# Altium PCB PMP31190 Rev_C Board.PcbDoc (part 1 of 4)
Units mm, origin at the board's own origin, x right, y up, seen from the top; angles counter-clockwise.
Board outline 175.26 x 91.44 mm, 4 copper layers (Top Layer, Mid-Layer 1, Mid-Layer 2, Bottom Layer), stack 1.473 mm thick; 252 components, 140 nets, 735 pads, 501 vias.
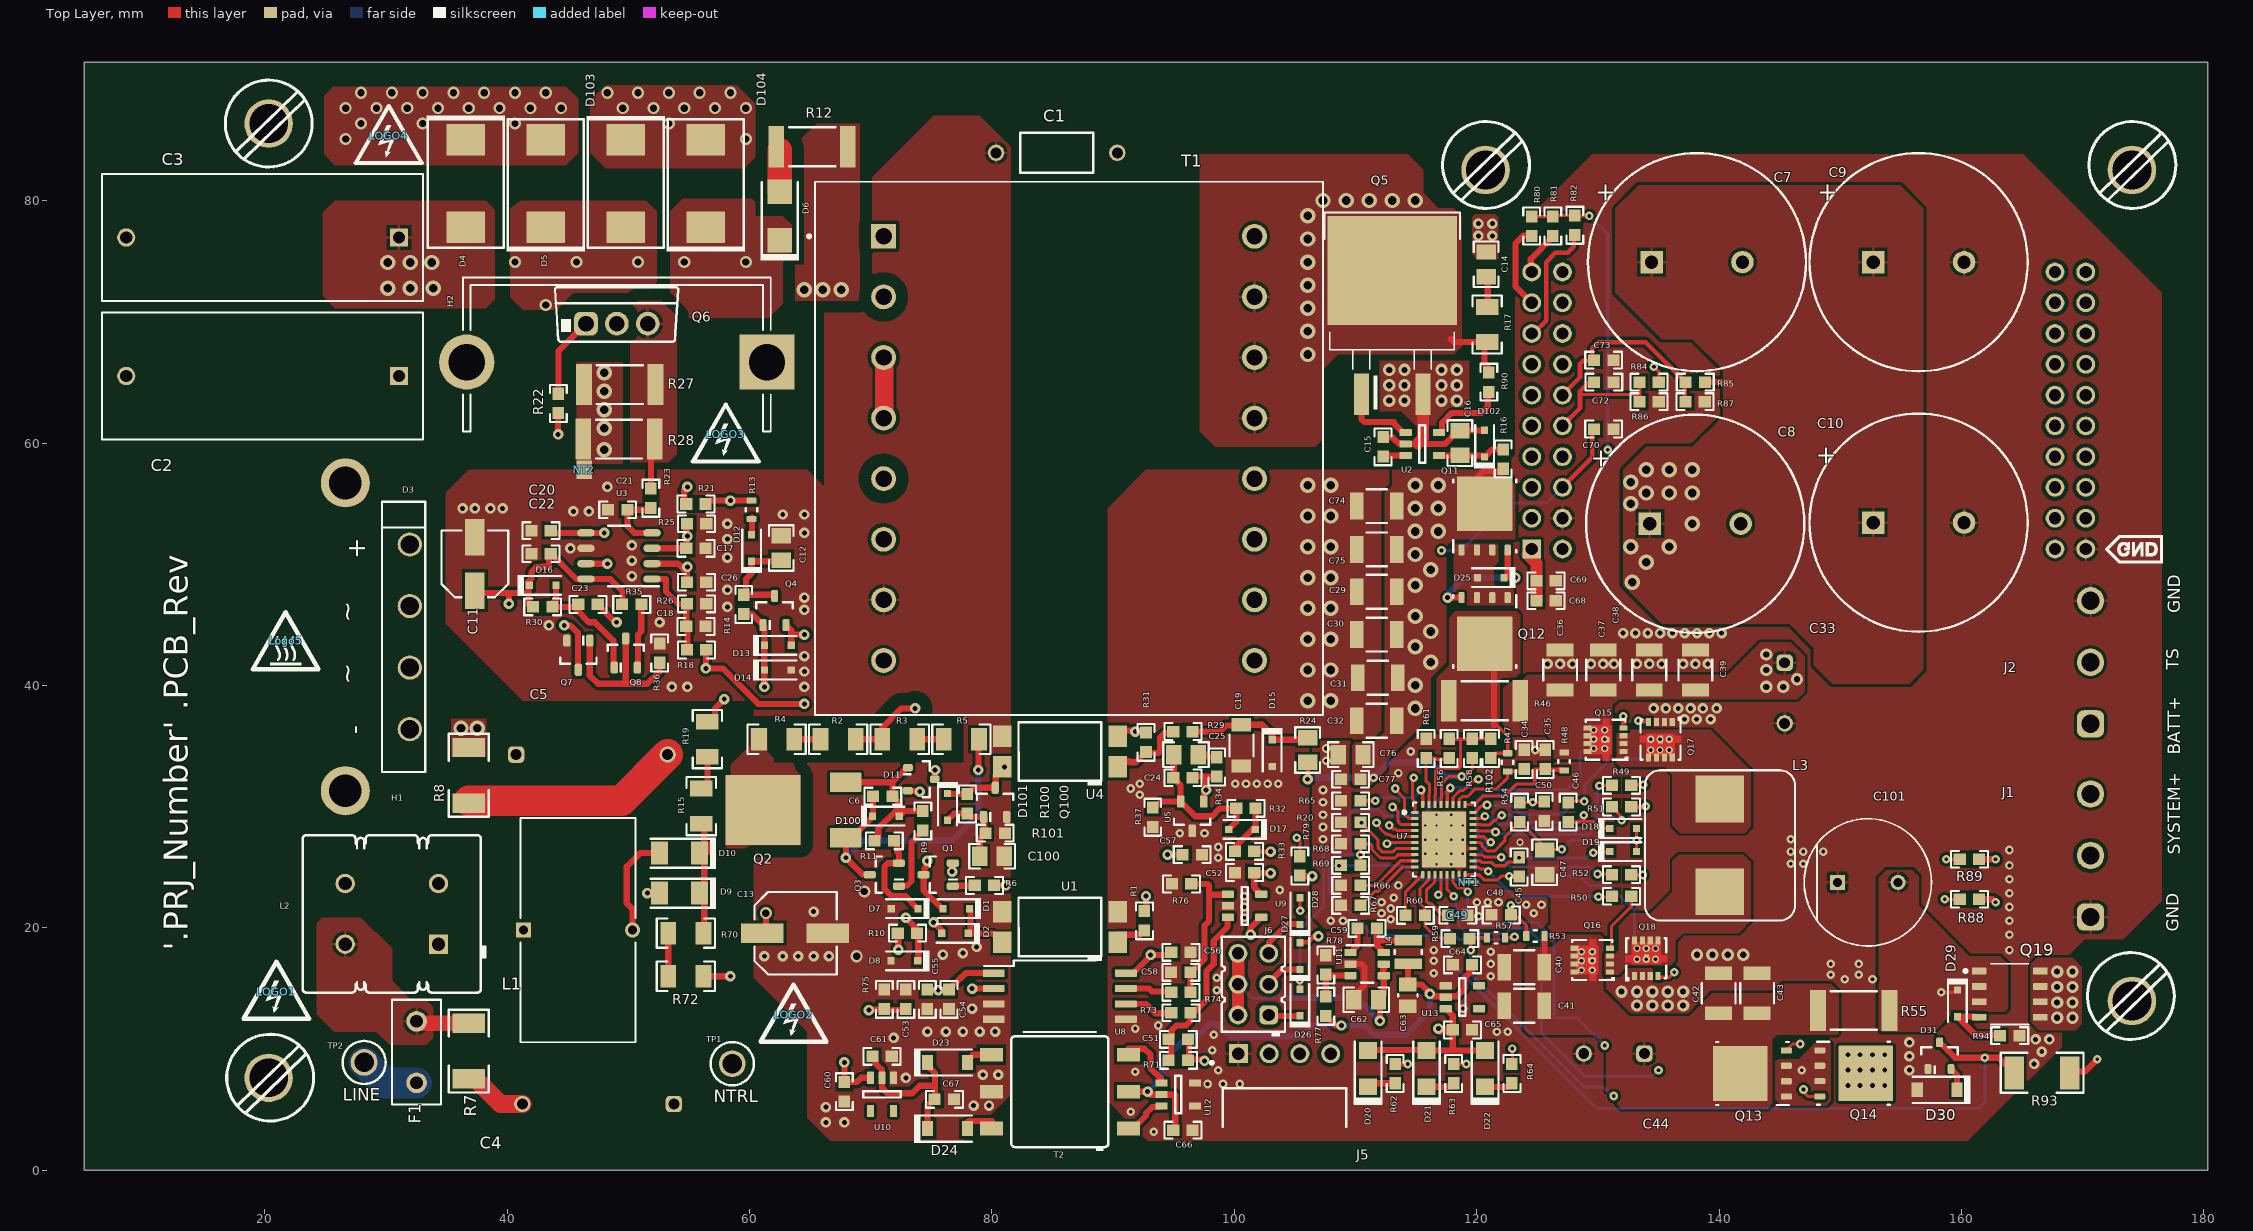
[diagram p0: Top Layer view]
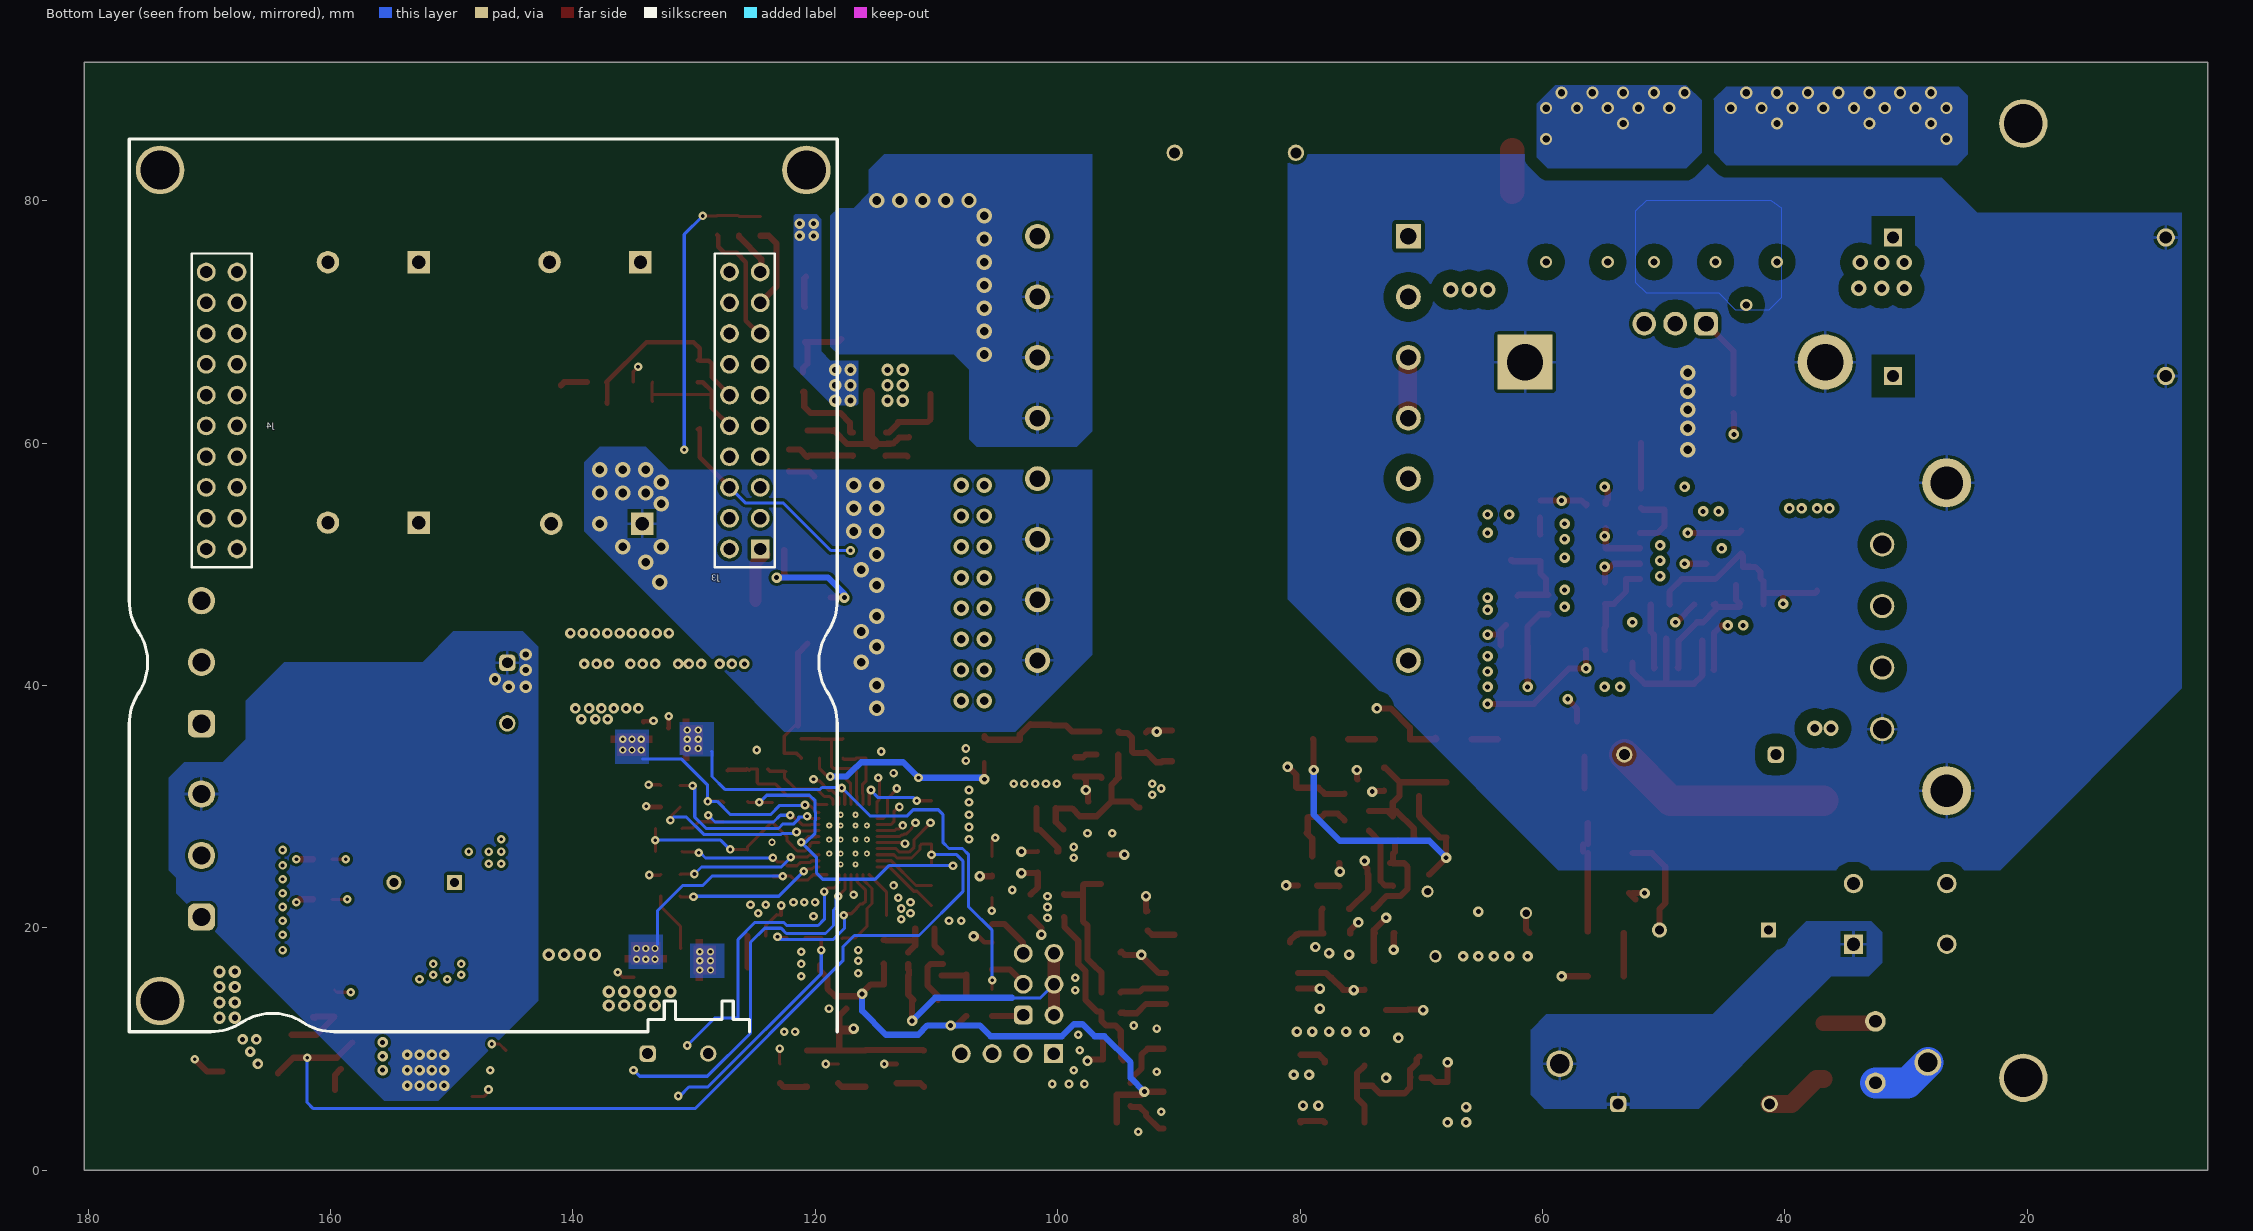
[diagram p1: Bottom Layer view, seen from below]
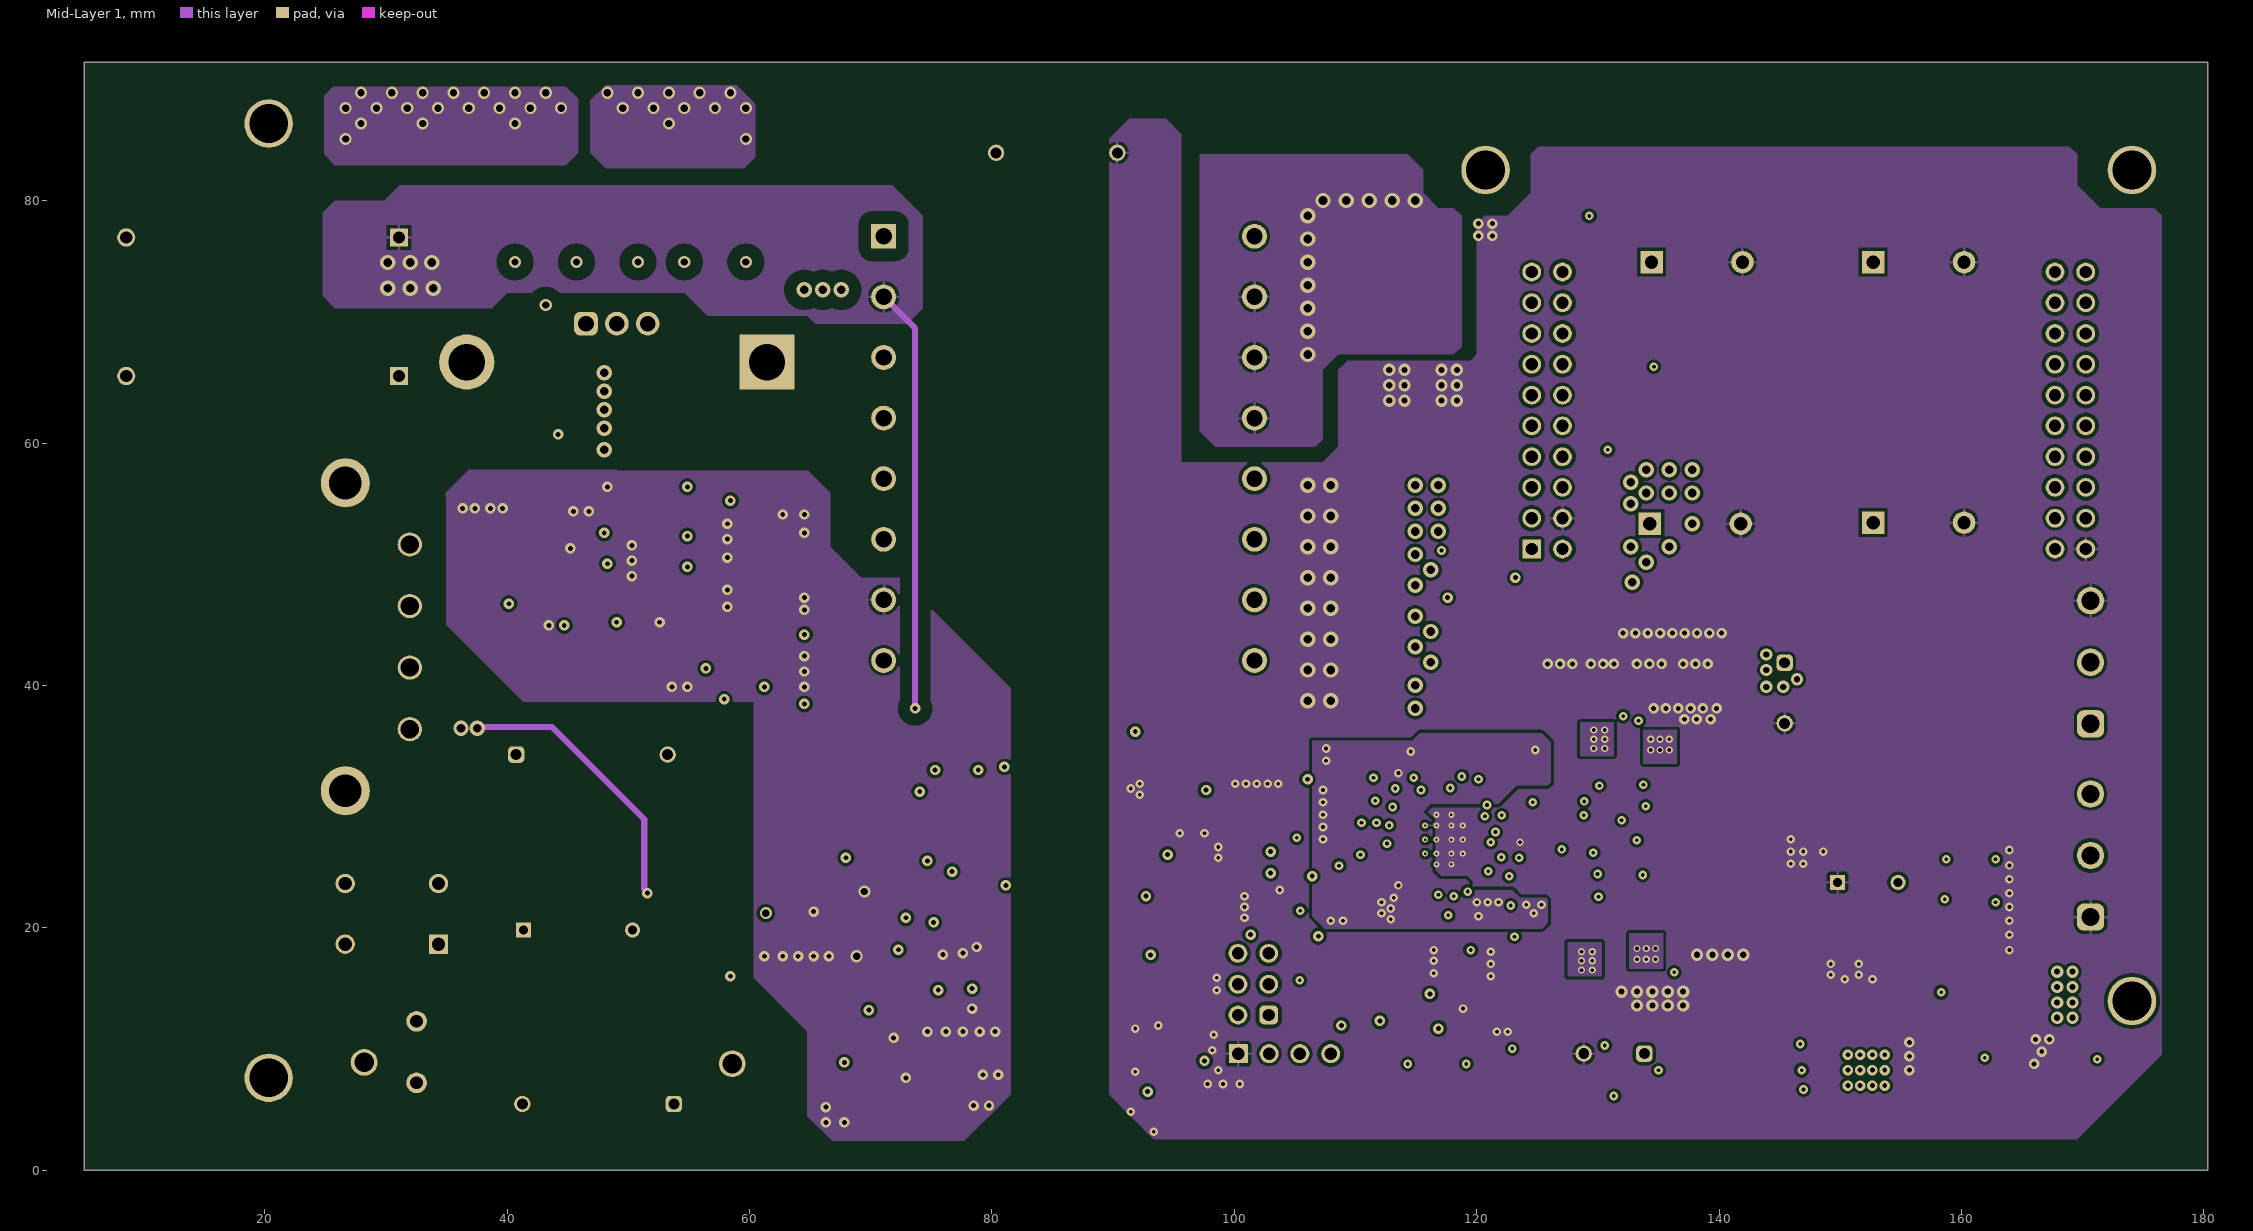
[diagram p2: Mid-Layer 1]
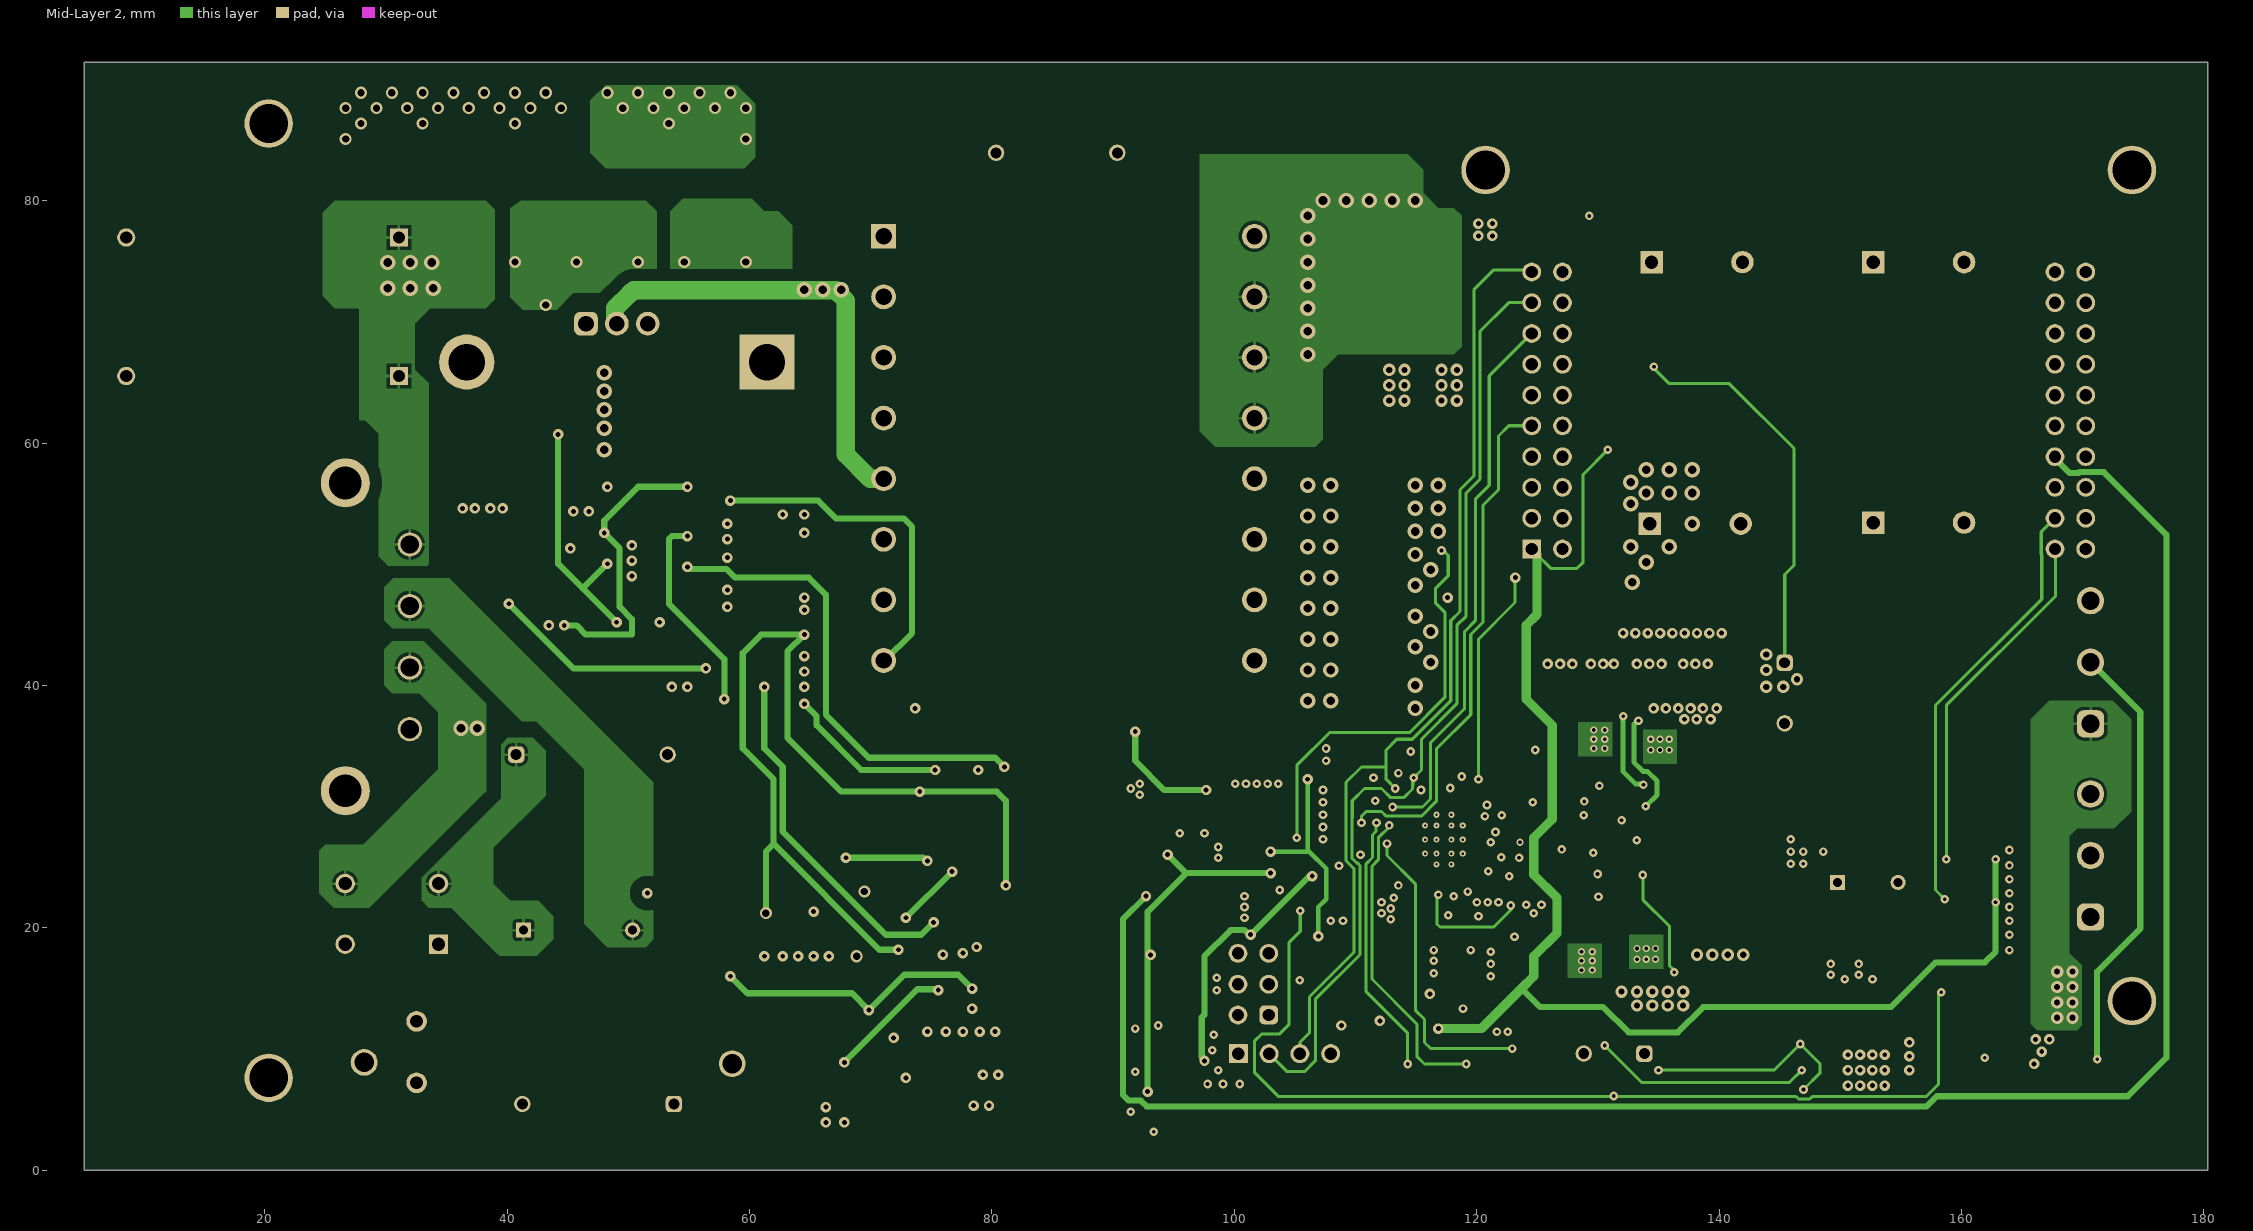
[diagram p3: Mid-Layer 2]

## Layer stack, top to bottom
Top Solder: solder mask 0.18, Solder Resist, Dk 3.5
Top Layer: signal copper 0.07
Dielectric1: prepreg 0.232, FR-4, Dk 4.8
Mid-Layer 1: signal copper 0.0356
Dielectric2: dielectric 0.71, FR-4, Dk 4.8
Mid-Layer 2: signal copper 0.0356
Dielectric3: dielectric 0.32, FR-4, Dk 4.8
Bottom Layer: signal copper 0.07
Bottom Solder: solder mask 0.018, Solder Resist, Dk 3.5

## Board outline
5.08,0 180.34,0 180.34,46.99 180.34,91.44 5.08,91.44

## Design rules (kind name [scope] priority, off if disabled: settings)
AcuteAngle [All] p1: minimum=4.50000000000000E+0001 checktracksonly=FALSE
AssemblyTestPointUsage [All] p1: valid=2
BoardOutlineClearance [All] p1: gap=0.381 ignorepadtopadclearanceinfootprint=FALSE
Clearance "Schematic Clearance Constraint_24" [InNet('NetD5_1')] p1: gap=1.016 ignorepadtopadclearanceinfootprint=FALSE
Clearance "Schematic Clearance Constraint_23" [InNet('NetD103_1')] p2: gap=1.016 ignorepadtopadclearanceinfootprint=FALSE
Clearance "Schematic Clearance Constraint_19" [InNet('PFC_off')] p3: gap=0.229 ignorepadtopadclearanceinfootprint=FALSE
Clearance "Schematic Clearance Constraint_18" [InNet('NetJ2_1')] p4: gap=0.229 ignorepadtopadclearanceinfootprint=FALSE
Clearance "Schematic Clearance Constraint_11" [InNet('BAT')] p5: gap=0.254 ignorepadtopadclearanceinfootprint=FALSE
Clearance "Schematic Clearance Constraint_10" [InNet('NetD30_1')] p6: gap=0.229 ignorepadtopadclearanceinfootprint=FALSE
Clearance "Schematic Clearance Constraint_4" [InNet('NetD29_2')] p7: gap=0.229 ignorepadtopadclearanceinfootprint=FALSE
Clearance "Schematic Clearance Constraint" [InNet('NetJ2_2')] p8: gap=0.229 ignorepadtopadclearanceinfootprint=FALSE
Clearance "Schematic Clearance Constraint_170" [InNet('NetQ18_4')] p9: gap=0.229 ignorepadtopadclearanceinfootprint=FALSE
Clearance "Schematic Clearance Constraint_169" [InNet('NetR52_2')] p10: gap=0.229 ignorepadtopadclearanceinfootprint=FALSE
Clearance "Schematic Clearance Constraint_168" [InNet('SDA')] p11: gap=0.229 ignorepadtopadclearanceinfootprint=FALSE
Clearance "Schematic Clearance Constraint_167" [InNet('NetC72_1')] p12: gap=0.229 ignorepadtopadclearanceinfootprint=FALSE
Clearance "Schematic Clearance Constraint_166" [InNet('NetC34_2')] p13: gap=0.229 ignorepadtopadclearanceinfootprint=FALSE
Clearance "Schematic Clearance Constraint_165" [InNet('NetJ4_39')] p14: gap=0.229 ignorepadtopadclearanceinfootprint=FALSE
Clearance "Schematic Clearance Constraint_164" [InNet('NetC45_1')] p15: gap=0.229 ignorepadtopadclearanceinfootprint=FALSE
Clearance "Schematic Clearance Constraint_163" [InNet('NetR66_2')] p16: gap=0.229 ignorepadtopadclearanceinfootprint=FALSE
Clearance "Schematic Clearance Constraint_162" [InNet('NetR60_2')] p17: gap=0.229 ignorepadtopadclearanceinfootprint=FALSE
Clearance "Schematic Clearance Constraint_161" [InNet('NetC49_1')] p18: gap=0.229 ignorepadtopadclearanceinfootprint=FALSE
Clearance "Schematic Clearance Constraint_160" [InNet('NetR63_2')] p19: gap=0.229 ignorepadtopadclearanceinfootprint=FALSE
Clearance "Schematic Clearance Constraint_159" [InNet('NetR58_1')] p20: gap=0.229 ignorepadtopadclearanceinfootprint=FALSE
Clearance "Schematic Clearance Constraint_158" [InNet('NetC48_2')] p21: gap=0.229 ignorepadtopadclearanceinfootprint=FALSE
Clearance "Schematic Clearance Constraint_157" [InNet('NetC73_1')] p22: gap=0.229 ignorepadtopadclearanceinfootprint=FALSE
Clearance "Schematic Clearance Constraint_155" [InNet('BAT_DRV')] p23: gap=0.229 ignorepadtopadclearanceinfootprint=FALSE
Clearance "Schematic Clearance Constraint_154" [InNet('NetR67_2')] p24: gap=0.229 ignorepadtopadclearanceinfootprint=FALSE
Clearance "Schematic Clearance Constraint_153" [InNet('NetR49_1')] p25: gap=0.229 ignorepadtopadclearanceinfootprint=FALSE
Clearance "Schematic Clearance Constraint_152" [InNet('NetC46_2')] p26: gap=0.229 ignorepadtopadclearanceinfootprint=FALSE
Clearance "Schematic Clearance Constraint_151" [InNet('NetQ17_4')] p27: gap=0.229 ignorepadtopadclearanceinfootprint=FALSE
Clearance "Schematic Clearance Constraint_150" [InNet('NetC46_1')] p28: gap=0.229 ignorepadtopadclearanceinfootprint=FALSE
Clearance "Schematic Clearance Constraint_149" [InNet('NetR56_1')] p29: gap=0.229 ignorepadtopadclearanceinfootprint=FALSE
Clearance "Schematic Clearance Constraint_148" [InNet('NetR62_2')] p30: gap=0.229 ignorepadtopadclearanceinfootprint=FALSE
Clearance "Schematic Clearance Constraint_147" [InNet('SCL')] p31: gap=0.229 ignorepadtopadclearanceinfootprint=FALSE
Clearance "Schematic Clearance Constraint_146" [InNet('NetR51_2')] p32: gap=0.229 ignorepadtopadclearanceinfootprint=FALSE
Clearance "Schematic Clearance Constraint_145" [InNet('NetC45_2')] p33: gap=0.229 ignorepadtopadclearanceinfootprint=FALSE
Clearance "Schematic Clearance Constraint_144" [InNet('NetC70_1')] p34: gap=0.229 ignorepadtopadclearanceinfootprint=FALSE
Clearance "Schematic Clearance Constraint_142" [InNet('NetR64_2')] p35: gap=0.229 ignorepadtopadclearanceinfootprint=FALSE
Clearance "Schematic Clearance Constraint_141" [InNet('NetD25_1')] p36: gap=0.229 ignorepadtopadclearanceinfootprint=FALSE
Clearance "Schematic Clearance Constraint_140" [InNet('SYSTEM')] p37: gap=0.229 ignorepadtopadclearanceinfootprint=FALSE
Clearance "Schematic Clearance Constraint_139" [InNet('NetR59_2')] p38: gap=0.229 ignorepadtopadclearanceinfootprint=FALSE
Clearance "Schematic Clearance Constraint_138" [InNet('NetJ4_40')] p39: gap=0.229 ignorepadtopadclearanceinfootprint=FALSE
Clearance "Schematic Clearance Constraint_137" [InNet('NetR50_2')] p40: gap=0.229 ignorepadtopadclearanceinfootprint=FALSE
Clearance "Schematic Clearance Constraint_136" [InNet('NetQ15_4')] p41: gap=0.229 ignorepadtopadclearanceinfootprint=FALSE
Clearance "Schematic Clearance Constraint_135" [InNet('NetC35_1')] p42: gap=0.229 ignorepadtopadclearanceinfootprint=FALSE
Clearance "Schematic Clearance Constraint_134" [InNet('NetD31_3')] p43: gap=0.229 ignorepadtopadclearanceinfootprint=FALSE
Clearance "Schematic Clearance Constraint_132" [InNet('NetQ16_4')] p44: gap=0.229 ignorepadtopadclearanceinfootprint=FALSE
Clearance "Schematic Clearance Constraint_131" [InNet('NetR65_2')] p45: gap=0.229 ignorepadtopadclearanceinfootprint=FALSE
Clearance "Schematic Clearance Constraint_130" [InNet('BQ_INT')] p46: gap=0.229 ignorepadtopadclearanceinfootprint=FALSE
Clearance "Schematic Clearance Constraint_129" [InNet('DRV_SUP')] p47: gap=0.229 ignorepadtopadclearanceinfootprint=FALSE
Clearance "Schematic Clearance Constraint_128" [InNet('AGND')] p48: gap=0.254 ignorepadtopadclearanceinfootprint=FALSE
Clearance "Schematic Clearance Constraint_126" [InNet('BQ_CE')] p49: gap=0.254 ignorepadtopadclearanceinfootprint=FALSE
Clearance "Schematic Clearance Constraint_125" [InNet('NetC4_2')] p50: gap=1.016 ignorepadtopadclearanceinfootprint=FALSE
Clearance "Schematic Clearance Constraint_124" [InNet('NetF1_1')] p51: gap=1.016 ignorepadtopadclearanceinfootprint=FALSE
Clearance "Schematic Clearance Constraint_123" [InNet('NetR15_1')] p52: gap=1.016 ignorepadtopadclearanceinfootprint=FALSE
Clearance "Schematic Clearance Constraint_122" [InNet('NetF1_2')] p53: gap=1.016 ignorepadtopadclearanceinfootprint=FALSE
Clearance "Schematic Clearance Constraint_121" [InNet('NetR3_1')] p54: gap=1.016 ignorepadtopadclearanceinfootprint=FALSE
Clearance "Schematic Clearance Constraint_120" [InNet('NetQ2_2')] p55: gap=1.016 ignorepadtopadclearanceinfootprint=FALSE
Clearance "Schematic Clearance Constraint_119" [InNet('NetQ6_2')] p56: gap=1.016 ignorepadtopadclearanceinfootprint=FALSE
Clearance "Schematic Clearance Constraint_118" [InNet('NetD4_1')] p57: gap=1.016 ignorepadtopadclearanceinfootprint=FALSE
Clearance "Schematic Clearance Constraint_117" [InNet('AC')] p58: gap=1.016 ignorepadtopadclearanceinfootprint=FALSE
Clearance "Schematic Clearance Constraint_116" [InNet('NetR2_1')] p59: gap=1.016 ignorepadtopadclearanceinfootprint=FALSE
Clearance "Schematic Clearance Constraint_115" [InNet('NetD6_2')] p60: gap=1.016 ignorepadtopadclearanceinfootprint=FALSE
Clearance "Schematic Clearance Constraint_114" [InNet('NetD3_2')] p61: gap=1.016 ignorepadtopadclearanceinfootprint=FALSE
Clearance "Schematic Clearance Constraint_113" [InNet('NetC5_1')] p62: gap=1.016 ignorepadtopadclearanceinfootprint=FALSE
Clearance "Schematic Clearance Constraint_112" [InNet('NetD3_3')] p63: gap=1.016 ignorepadtopadclearanceinfootprint=FALSE
Clearance "Schematic Clearance Constraint_111" [InNet('NetR70_1')] p64: gap=1.016 ignorepadtopadclearanceinfootprint=FALSE
Clearance "Schematic Clearance Constraint_110" [InNet('NetD6_1')] p65: gap=1.016 ignorepadtopadclearanceinfootprint=FALSE
Clearance "Schematic Clearance Constraint_109" [InNet('NetC2_1')] p66: gap=1.016 ignorepadtopadclearanceinfootprint=FALSE
Clearance "Schematic Clearance Constraint_108" [InNet('NetC4_1')] p67: gap=1.016 ignorepadtopadclearanceinfootprint=FALSE
Clearance "Schematic Clearance Constraint_107" [InNet('NetR77_1')] p68: gap=0.254 ignorepadtopadclearanceinfootprint=FALSE
Clearance "Schematic Clearance Constraint_105" [InNet('NetC51_1')] p69: gap=0.254 ignorepadtopadclearanceinfootprint=FALSE
Clearance "Schematic Clearance Constraint_104" [InNet('NetC62_1')] p70: gap=0.254 ignorepadtopadclearanceinfootprint=FALSE
Clearance "Schematic Clearance Constraint_103" [InNet('NetQ1_1')] p71: gap=0.254 ignorepadtopadclearanceinfootprint=FALSE
Clearance "Schematic Clearance Constraint_100" [InNet('PFC_off1')] p72: gap=0.254 ignorepadtopadclearanceinfootprint=FALSE
Clearance "Schematic Clearance Constraint_98" [InNet('NetD7_1')] p73: gap=0.254 ignorepadtopadclearanceinfootprint=FALSE
Clearance "Schematic Clearance Constraint_93" [InNet('NetC18_1')] p74: gap=0.254 ignorepadtopadclearanceinfootprint=FALSE
Clearance "Schematic Clearance Constraint_92" [InNet('+3V3')] p75: gap=0.254 ignorepadtopadclearanceinfootprint=FALSE
Clearance "Schematic Clearance Constraint_89" [InNet('NetD12_2')] p76: gap=0.254 ignorepadtopadclearanceinfootprint=FALSE
Clearance "Schematic Clearance Constraint_86" [InNet('NetQ3_1')] p77: gap=0.254 ignorepadtopadclearanceinfootprint=FALSE
Clearance "Schematic Clearance Constraint_83" [InNet('NetR13_2')] p78: gap=0.254 ignorepadtopadclearanceinfootprint=FALSE
Clearance "Schematic Clearance Constraint_79" [InNet('NetD23_2')] p79: gap=0.254 ignorepadtopadclearanceinfootprint=FALSE
Clearance "Schematic Clearance Constraint_78" [InNet('BAT_SRC')] p80: gap=0.254 ignorepadtopadclearanceinfootprint=FALSE
Clearance "Schematic Clearance Constraint_75" [InNet('Bias')] p81: gap=0.254 ignorepadtopadclearanceinfootprint=FALSE
Clearance "Schematic Clearance Constraint_73" [InNet('NetC19_1')] p82: gap=0.254 ignorepadtopadclearanceinfootprint=FALSE
Clearance "Schematic Clearance Constraint_71" [InNet('NetD25_2')] p83: gap=0.254 ignorepadtopadclearanceinfootprint=FALSE
Clearance "Schematic Clearance Constraint_69" [InNet('NetC40_1')] p84: gap=0.254 ignorepadtopadclearanceinfootprint=FALSE
Clearance "Schematic Clearance Constraint_67" [InNet('NetC6_2')] p85: gap=0.254 ignorepadtopadclearanceinfootprint=FALSE
Clearance "Schematic Clearance Constraint_63" [InNet('NetC61_2')] p86: gap=0.254 ignorepadtopadclearanceinfootprint=FALSE
Clearance "Schematic Clearance Constraint_61" [InNet('NetD17_1')] p87: gap=0.254 ignorepadtopadclearanceinfootprint=FALSE
Clearance "Schematic Clearance Constraint_60" [InNet('NetQ8_2')] p88: gap=0.254 ignorepadtopadclearanceinfootprint=FALSE
Clearance "Schematic Clearance Constraint_59" [InNet('+5Vs')] p89: gap=0.254 ignorepadtopadclearanceinfootprint=FALSE
Clearance "Schematic Clearance Constraint_57" [InNet('NetT2_1')] p90: gap=0.254 ignorepadtopadclearanceinfootprint=FALSE
Clearance "Schematic Clearance Constraint_55" [InNet('NetC53_2')] p91: gap=0.254 ignorepadtopadclearanceinfootprint=FALSE
Clearance "Schematic Clearance Constraint_54" [InNet('NetT2_3')] p92: gap=0.254 ignorepadtopadclearanceinfootprint=FALSE
Clearance "Schematic Clearance Constraint_51" [InNet('NetC20_1')] p93: gap=0.254 ignorepadtopadclearanceinfootprint=FALSE
Clearance "Schematic Clearance Constraint_49" [InNet('NetC17_1')] p94: gap=0.254 ignorepadtopadclearanceinfootprint=FALSE
Clearance "Schematic Clearance Constraint_47" [InNet('FB')] p95: gap=0.254 ignorepadtopadclearanceinfootprint=FALSE
Clearance "Schematic Clearance Constraint_44" [InNet('NetQ12_5')] p96: gap=0.254 ignorepadtopadclearanceinfootprint=FALSE
Clearance "Schematic Clearance Constraint_41" [InNet('NetC12_1')] p97: gap=0.254 ignorepadtopadclearanceinfootprint=FALSE
Clearance "Schematic Clearance Constraint_39" [InNet('NetC15_1')] p98: gap=0.254 ignorepadtopadclearanceinfootprint=FALSE
Clearance "Schematic Clearance Constraint_38" [InNet('NetQ6_3')] p99: gap=0.254 ignorepadtopadclearanceinfootprint=FALSE
Clearance "Schematic Clearance Constraint_37" [InNet('+5Vp')] p100: gap=0.254 ignorepadtopadclearanceinfootprint=FALSE
Clearance "Schematic Clearance Constraint_36" [InNet('NetC23_1')] p101: gap=0.254 ignorepadtopadclearanceinfootprint=FALSE
Clearance "Schematic Clearance Constraint_35" [InNet('NetQ6_1')] p102: gap=0.254 ignorepadtopadclearanceinfootprint=FALSE
Clearance "Schematic Clearance Constraint_34" [InNet('NetQ5_4')] p103: gap=0.254 ignorepadtopadclearanceinfootprint=FALSE
Clearance "Schematic Clearance Constraint_32" [InNet('NetQ5_1')] p104: gap=0.254 ignorepadtopadclearanceinfootprint=FALSE
Clearance "Schematic Clearance Constraint_31" [InNet('NetD8_1')] p105: gap=0.254 ignorepadtopadclearanceinfootprint=FALSE
Clearance "Schematic Clearance Constraint_30" [InNet('NetC24_2')] p106: gap=0.254 ignorepadtopadclearanceinfootprint=FALSE
Clearance "Schematic Clearance Constraint_29" [InNet('NetC16_1')] p107: gap=0.254 ignorepadtopadclearanceinfootprint=FALSE
Clearance "Schematic Clearance Constraint_28" [InNet('VDD')] p108: gap=0.254 ignorepadtopadclearanceinfootprint=FALSE
Clearance "Schematic Clearance Constraint_26" [InNet('+24V')] p109: gap=0.254 ignorepadtopadclearanceinfootprint=FALSE
Clearance "Schematic Clearance Constraint_22" [InNet('NetQ7_1')] p110: gap=0.254 ignorepadtopadclearanceinfootprint=FALSE
Clearance "Schematic Clearance Constraint_21" [InNet('NetC21_1')] p111: gap=0.254 ignorepadtopadclearanceinfootprint=FALSE
Clearance "Schematic Clearance Constraint_20" [InNet('VAC-u')] p112: gap=0.254 ignorepadtopadclearanceinfootprint=FALSE
Clearance "Schematic Clearance Constraint_17" [InNet('NetR74_1')] p113: gap=0.254 ignorepadtopadclearanceinfootprint=FALSE
Clearance "Schematic Clearance Constraint_16" [InNet('NetC58_1')] p114: gap=0.254 ignorepadtopadclearanceinfootprint=FALSE
Clearance "Schematic Clearance Constraint_14" [InNet('NetD24_2')] p115: gap=0.254 ignorepadtopadclearanceinfootprint=FALSE
Clearance "Schematic Clearance Constraint_13" [InNet('NetC59_2')] p116: gap=0.254 ignorepadtopadclearanceinfootprint=FALSE
Clearance "Schematic Clearance Constraint_9" [InNet('NetC24_1')] p117: gap=0.254 ignorepadtopadclearanceinfootprint=FALSE
Clearance "Schematic Clearance Constraint_8" [InNet('NetR73_1')] p118: gap=0.254 ignorepadtopadclearanceinfootprint=FALSE
Clearance "Schematic Clearance Constraint_7" [InNet('REG_N')] p119: gap=0.229 ignorepadtopadclearanceinfootprint=FALSE
Clearance "Schematic Clearance Constraint_6" [InNet('NetC23_2')] p120: gap=0.254 ignorepadtopadclearanceinfootprint=FALSE
Clearance "Schematic Clearance Constraint_5" [InNet('NetC25_2')] p121: gap=0.254 ignorepadtopadclearanceinfootprint=FALSE
Clearance "Schematic Clearance Constraint_3" [InNet('NetR1_1')] p122: gap=0.254 ignorepadtopadclearanceinfootprint=FALSE
Clearance "Schematic Clearance Constraint_2" [InNet('NetR29_1')] p123: gap=0.254 ignorepadtopadclearanceinfootprint=FALSE
Clearance "Schematic Clearance Constraint_1" [InNet('PFC_off2')] p124: gap=0.254 ignorepadtopadclearanceinfootprint=FALSE
Clearance HV_ALL [InNetClass('HV')] p125: gap=1.016 ignorepadtopadclearanceinfootprint=FALSE
Clearance Clearance_1 [InNet('NetR10_2') vs InNet('PGND')] p126: gap=1.524 ignorepadtopadclearanceinfootprint=FALSE except(0: Arc-Hole Track-Hole SMDPad-Hole THPad-Hole Via-Hole Fill-Hole Poly-Hole Region-Hole Text-Hole)
Clearance Clearance_390V_Discrete [InNet('390V') vs InNet('NetR20_1') Or InNet('NetR86_2') Or InNet('NetQ3_1') Or InNet('SW') Or IsKeepOut] p127: gap=0.61 ignorepadtopadclearanceinfootprint=FALSE except(0: Arc-Hole Track-Hole SMDPad-Hole THPad-Hole Via-Hole Fill-Hole Poly-Hole Region-Hole Text-Hole)
Clearance Clearance_390V [InNet('390V')] p128: gap=1.5 ignorepadtopadclearanceinfootprint=FALSE except(0: Arc-Hole Track-Hole SMDPad-Hole THPad-Hole Via-Hole Fill-Hole Poly-Hole Region-Hole Text-Hole)
Clearance Clearance_MTG [InPadClass('MTG')] p129: gap=0.762 ignorepadtopadclearanceinfootprint=FALSE except(0: Arc-Hole Track-Hole SMDPad-Hole THPad-Hole Via-Hole Fill-Hole Poly-Hole Region-Hole Text-Hole)
Clearance Clearance_Keepouts [IsKeepOut] p130: gap=0.381 ignorepadtopadclearanceinfootprint=FALSE
Clearance Clearance_Poly [InPolygon] p131: gap=0.381 ignorepadtopadclearanceinfootprint=FALSE except(0: Arc-Hole Track-Hole SMDPad-Hole THPad-Hole Via-Hole Fill-Hole Poly-Hole Region-Hole Text-Hole; 0.203: Track-Poly SMDPad-Poly; 0.305: THPad-Poly; 0.508: Poly-Poly)
Clearance [All] p132: gap=0.203 ignorepadtopadclearanceinfootprint=FALSE
ComponentClearance ComponentClearance_MountingHoles_FiducialMarks [InComponentClass('Mounting Holes') vs InComponentClass('FiducialMark')] p1: gap=0.254 collisioncheckmode=3 verticalgap=0.254 showdistances=FALSE
ComponentClearance ComponentClearance_Shunt [InComponentClass('Header') vs InComponentClass('Shunt')] p2: gap=0 collisioncheckmode=3 verticalgap=0 showdistances=FALSE
ComponentClearance ComponentClearance_Logo [InComponentClass('Logo')] p3: gap=0.127 collisioncheckmode=3 verticalgap=0.127 showdistances=FALSE
ComponentClearance ComponentClearance_ScrewToNut [(HasFootprint('NY PMS 440 0025 PH')) vs (HasFootprint('Keystone_1902C'))] p4: gap=0.127 collisioncheckmode=3 verticalgap=0.127 showdistances=FALSE
ComponentClearance ComponentClearance_MountingHoles [InComponentClass('Mounting Holes')] p5: gap=1.27 collisioncheckmode=3 verticalgap=2540 showdistances=FALSE
ComponentClearance ComponentClearance_SmallPassives [HasFootprint('0201*') or HasFootprint('0402*') or HasFootprint('0508') or HasFootprint('0603*') or HasFootprint('0612') or HasFootprint('0805*') or HasFootprint('0815*') or HasFootprint('0830*') or HasFootprint('1206*') or HasFootprint('1210*') or HasFootprint('1808*') or HasFootprint('1812*') or HasFootprint('1825*') or HasFootprint('2010*') or HasFootprint('2220*') or HasFootprint('2225*') or HasFootprint('2512*') or HasFootprint('2728*') or HasFootprint('3518*') vs HasFootprint('0201*') or HasFootprint('0402*') or HasFootprint('0508') or HasFootprint('0603*') or HasFootprint('0612') or HasFootprint('0805*') or HasFootprint('0815*') or HasFootprint('0830*') or HasFootprint('1206*') or HasFootprint('1210*') or HasFootprint('1808*') or HasFootprint('1812*') or HasFootprint('1825*') or HasFootprint('2010*') or HasFootprint('2220*') or HasFootprint('2225*') or HasFootprint('2512*') or HasFootprint('2728*') or HasFootprint('3518*')] p6: gap=0.254 collisioncheckmode=3 verticalgap=0.254 showdistances=FALSE
ComponentClearance ComponentClearance_THtoSMT [IsThruComponent vs IsSMTComponent] p7: gap=0.127 collisioncheckmode=3 verticalgap=0.127 showdistances=FALSE
ComponentClearance ComponentClearance_THtoTH [IsThruComponent vs IsThruComponent] p8: gap=0.254 collisioncheckmode=3 verticalgap=0.254 showdistances=FALSE
ComponentClearance [All] p9: gap=0.254 collisioncheckmode=3 verticalgap=0.254 showdistances=FALSE
DiffPairsRouting [All] p1: maxlimit=2.54 minlimit=0.254 mostfreqgap=0.254 toplayer_minwidth=0.381 toplayer_maxwidth=0.381 toplayer_prefwidth=0.381 midlayer1_minwidth=0.381 midlayer1_maxwidth=0.381 midlayer1_prefwidth=0.381 midlayer2_minwidth=0.381 midlayer2_maxwidth=0.381 midlayer2_prefwidth=0.381 bottomlayer_minwidth=0.381 bottomlayer_maxwidth=0.381 bottomlayer_prefwidth=0.381 maxuncoupledlength=25.4
FabricationTestPointUsage TestPointUsage [All] p1: valid=2 allowmultiple=FALSE
FabricationTestpoint Testpoint [All] p1: side=3 testpointundercomponent=TRUE minsize=1.016 maxsize=2.54 preferedsize=1.524 minholesize=0 maxholesize=1.016 preferedholesize=0.813 testpointgrid=0.025 allowsidetop=TRUE allowsidebottom=TRUE usegrid=TRUE gridtolerance=0
FanoutControl Fanout_LCC [IsLCC] p1: bgadir=Out bgaviamode=Centered fanoutstyle=Auto fanoutdirection=Alternating viagrid=0.025 // Fanout_LCC (Default Rule)
FanoutControl Fanout_BGA [IsBGA] p2: bgadir=Out bgaviamode=Centered fanoutstyle=Auto fanoutdirection=Alternating viagrid=0.025 // Fanout_BGA (Default Rule)
FanoutControl Fanout_Default [All] p4: bgadir=Out bgaviamode=Centered fanoutstyle=Auto fanoutdirection=Alternating viagrid=0.025 // Fanout_Default (Default Rule)
FanoutControl Fanout_Small [(CompPinCount < 5)] p5: bgadir=Out bgaviamode=Centered fanoutstyle=Auto fanoutdirection=OutThenIn viagrid=0.025 // Fanout_Small (Default Rule)
Height [All] p1: minheight=0 maxheight=38 prefheight=12.7
HoleSize [All] p1: absolutevalues=TRUE maxlimit=6.375 minlimit=0.2 maxpercent=80.000 minpercent=20.000
MinimumAnnularRing MinimumAnnularRing_ThermalPadVias [IsVia and InAnyComponent] p1: minimumring=0.15
MinimumAnnularRing [All] p2: minimumring=0.127
MinimumSolderMaskSliver MinimumSolderMaskSliver_Logo [InComponentClass('Logo') vs InComponentClass('Logo')] p1: minsoldermaskwidth=0.018
MinimumSolderMaskSliver [All] p2: minsoldermaskwidth=0.1
PlaneConnect [All] p1: planeconnectstyle=Relief reliefexpansion=0.254 reliefentries=4 reliefconductorwidth=0.254 reliefairgap=0.254
PolygonConnect PolygonConnect_2 [All vs IsNamedPolygon('MID-LAYER_1_NETC1_2_P014')] p1: thpad.connectstyle=Relief thpad.reliefconductorwidth=0.254 thpad.reliefentries=4 thpad.polygonreliefangle="90 Angle" thpad.airgapwidth=0.254 smdpad.connectstyle=Direct smdpad.reliefconductorwidth=0.254 smdpad.reliefentries=4 smdpad.polygonreliefangle="90 Angle" smdpad.airgapwidth=0.254 via.connectstyle=Direct via.reliefconductorwidth=0.254 via.reliefentries=4 via.polygonreliefangle="90 Angle" via.airgapwidth=0.254
PolygonConnect PolygonConnect_1 [All vs IsNamedPolygon('MID-LAYER_1_NETC1_2_P014')] p2: thpad.connectstyle=Relief thpad.reliefconductorwidth=0.254 thpad.reliefentries=4 thpad.polygonreliefangle="90 Angle" thpad.airgapwidth=0.254 smdpad.connectstyle=Direct smdpad.reliefconductorwidth=0.254 smdpad.reliefentries=4 smdpad.polygonreliefangle="90 Angle" smdpad.airgapwidth=0.254 via.connectstyle=Relief via.reliefconductorwidth=0.254 via.reliefentries=4 via.polygonreliefangle="90 Angle" via.airgapwidth=0.254
PolygonConnect [All] p3: thpad.connectstyle=Relief thpad.reliefconductorwidth=0.254 thpad.reliefentries=4 thpad.polygonreliefangle="90 Angle" thpad.airgapwidth=0.254 smdpad.connectstyle=Direct smdpad.reliefconductorwidth=0.254 smdpad.reliefentries=4 smdpad.polygonreliefangle="90 Angle" smdpad.airgapwidth=0.254 via.connectstyle=Direct via.reliefconductorwidth=0.254 via.reliefentries=4 via.polygonreliefangle="90 Angle" via.airgapwidth=0.254
RoutingVias [All] p1: holewidth=0.381 width=0.762 viastyle="Through Hole" minholewidth=0.2 minwidth=0.5 maxholewidth=1.016 maxwidth=1.651
RoutingVias ThermalPadVias [IsVia and InAnyComponent] p2: holewidth=0.2 width=0.5 viastyle="Through Hole" minholewidth=0.2 minwidth=0.5 maxholewidth=0.33 maxwidth=0.6
SilkToBoardRegionClearance [Not ((IsComment or IsDesignator) And (Hide <> 'False')) and not InRegion(1000,500,4000,800)] p1:
SilkToSilkClearance SilkToSilkClearance_Pb-FreeLogo [(HasFootprint('Pb-Free_Overlay_Medium') OR HasFootprint('Pb-Free_Overlay_Small')) vs (HasFootprint('Pb-Free_Overlay_Medium') OR HasFootprint('Pb-Free_Overlay_Small'))] p1: silktosilkclearance=0
SilkToSilkClearance [All] p2: silktosilkclearance=0.102
SilkToSolderMaskClearance SilkToComponentPadClearance [IsPad and InAnycomponent] p1: minsilkscreentomaskgap=0.127 clearancetoexposedcopper=TRUE
SilkToSolderMaskClearance "Silk to Solder Mask Opening" [All] p2: minsilkscreentomaskgap=0.102 clearancetoexposedcopper=FALSE
SolderMaskExpansion [All] p1: expansion=0.064 istentingtop=FALSE
Width [All] p1: maxlimit=2.54 minlimit=0.152 preferedwidth=0.254 checkconnectedcopper=TRUE
14 further rules are at their usual default settings.

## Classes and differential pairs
component class Header: J6
component class "PMP31190 Rev_C Schematic - PFC Flyback": !PCB1 C1 C2 C3 C4 C5 C6 C7 C8 C9 C10 C11 C12 C13 C14 C15 C16 C17 C18 C19 C20 C21 C22 C23 C24 C25 C26 C74 C75 C100 D1 D2 D3 D4 D5 D6 D7 D8 D9 D10 D11 D12 D13 D14 D15 D16 D17 D100 D101 D102 D103 D104 F1 H1 H2 L1 L2 LOGO1 LOGO2 LOGO3 LOGO4 Logo5 NT2 Q1 Q2 Q3 Q4 Q5 Q6 Q7 Q8 Q100 R1 R2 R3 R4 R5 R6 R7 R8 R9 R10 R11 R12 R13 R14 R15 R16 R17 R18 R19 R21 R22 R23 R24 R25 R26 R27 R28 R29 R30 R31 R32 R33 R34 R35 R36 R37 R90 R100 R101 T1 TP1 TP2 U1 U2 U3 U4 U5
component class "PMP31190 Rev_B Schematic - LaunchPad Interface": C51 C52 C53 C54 C55 C56 C57 C58 C59 C60 C61 C62 C63 C64 C65 C66 C67 C68 C69 C70 C72 C73 D23 D24 D26 D27 D28 J3 J4 J6 L4 R20 R70 R71 R72 R73 R74 R75 R76 R77 R78 R79 R80 R81 R82 R84 R85 R86 R87 R88 R89 T2 U8 U9 U10 U11 U12 U13
component class "PMP31190 Rev_B Schematic - Charger": C29 C30 C31 C32 C33 C34 C35 C36 C37 C38 C39 C40 C41 C42 C43 C44 C45 C46 C47 C48 C49 C50 C76 C77 C101 D18 D19 D20 D21 D22 D25 D29 D30 D31 J1 J2 J5 L3 NT1 Q11 Q12 Q13 Q14 Q15 Q16 Q17 Q18 Q19 R46 R47 R48 R49 R50 R51 R52 R53 R54 R55 R56 R57 R58 R59 R60 R61 R62 R63 R64 R65 R66 R67 R68 R69 R93 R94 R102 U7

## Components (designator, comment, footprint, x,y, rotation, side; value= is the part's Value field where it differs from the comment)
C1 "DE1E3RA222MA4BN01F" DE1_600x400x900 85.344,83.947 r180 top value=2200pF
C2 "B32923C3684M" B32923_16.5mm_10.5 19.812,65.532 r180 top value=0.68uF
C3 "B32923C3684M" B32923_16.5mm_10.5 19.812,76.962 r180 top value=0.68uF
C4 "890334024003" WCAP-FTX2_1500x850 47.498,5.461 r180 top value=0.33uF
C5 "890334024003" WCAP-FTX2_1500x850 46.99,34.29 r0 top value=0.33uF
C6 "885012206083" 0603 70.993,30.861 r0 top value=1000pF
C7 "50YXS2200MEFC18X31.5" CAPPR7.5-18x31.5 138.176,74.93 r0 top value=2200uF
C8 "50YXS2200MEFC18X31.5" CAPPR7.5-18x31.5 138.032,53.343 r0 top value=2200uF
C9 "50YXS2200MEFC18X31.5" CAPPR7.5-18x31.5 156.464,74.927 r0 top value=2200uF
C10 "50YXS2200MEFC18X31.5" CAPPR7.5-18x31.5 156.464,53.432 r0 top value=2200uF
C11 "865080542006" CAPSMT_62_E55 37.33,50.024 r90 top value=22uF
C12 "885012207103" 0805_HV 62.605,51.34 r90 top value=1uF
C13 "EEEFK1V101XP" CAPSMT_62_F80 63.754,19.558 r0 top value=100uF
C14 "DNP" 0805_HV 120.771,74.743 r90 top
C15 "885012106018" 0603 112.268,59.69 r90 top value=2.2uF
C16 "885012207103" 0805_HV 118.618,59.995 r90 top value=1uF
C17 "885012206083" 0603 55.574,51.309 r0 top value=1000pF
C18 "885012206095" 0603 55.574,44.864 r0 top value=0.1uF
C19 "885012108021" 1206_180 100.584,35.052 r270 top value=10uF
C20 "885012006051" 0603 42.789,52.779 r180 top value=10pF
C21 "885012006057" 0603 49.114,54.494 r180 top value=100pF
C22 "885012206095" 0603 42.789,50.865 r180 top value=0.1uF
C23 "885012006051" 0603 46.667,46.68 r0 top value=10pF
C24 "885012206093" 0603 95.758,32.385 r180 top value=0.047uF
C25 "CGA4J3X7R1E225K125AB" 0805_HV 96.012,34.29 r0 top value=2.2uF
C26 "885012206089" 0603 55.626,48.514 r0 top value=0.01uF
C29 "885012209073" 1210_280 111.76,47.715 r180 top value=10uF
C30 "885012209073" 1210_280 111.756,44.196 r180 top value=10uF
C31 "885012209073" 1210_280 111.831,40.64 r180 top value=10uF
C32 "885012209073" 1210_280 111.756,37.092 r180 top value=10uF
C33 "870135675003" WCAP-PTHT_1000x1250 145.412,39.37 r270 top value=100uF
C34 "CGA3E3X7R1H474K080AE" 0603 123.914,33.895 r270 top value=0.47uF
C35 "CGA3E3X7R1H474K080AE" 0603 125.652,33.895 r90 top value=0.47uF
C36 "885012209073" 1210_280 126.873,41.275 r90 top value=10uF
C37 "885012209073" 1210_280 130.429,41.275 r90 top value=10uF
C38 "885012209073" 1210_280 134.239,41.275 r90 top value=10uF
C39 "885012209073" 1210_280 138.049,41.275 r90 top value=10uF
C40 "885012209073" 1210_280 123.925,16.747 r180 top value=10uF
C41 "885012209073" 1210_280 123.925,13.568 r180 top value=10uF
C42 "885012209073" 1210_280 139.954,14.605 r90 top value=10uF
C43 "885012209073" 1210_280 143.129,14.605 r90 top value=10uF
C44 "870135675003" WCAP-PTHT_1000x1250 131.33,9.618 r180 top value=100uF
C45 "885012206095" 0603 123.495,25.019 r90 top value=0.1uF
C46 "885012206095" 0603 127.541,29.539 r270 top value=0.1uF
C47 "885012107018" 0805_HV 125.603,25.4 r270 top value=4.7uF
C48 "885012206095" 0603 122.022,21.057 r0 top value=0.1uF
C49 "885012206095" 0603 118.44,21.031 r0 top value=0.1uF
C50 "885012206076" 0603 125.575,29.608 r90 top value=1uF
C51 "885012206083" 0603 95.377,10.795 r0 top value=1000pF
C52 "885012206095" 0603 100.844,24.558 r0 top value=0.1uF
C53 "885012206076" 0603 72.898,14.097 r270 top value=1uF
C54 "885012206076" 0603 76.454,14.097 r90 top value=1uF
C55 "885012206095" 0603 74.676,14.097 r90 top value=0.1uF
C56 "885012206095" 0603 95.591,17.967 r180 top value=0.1uF
C57 "885012206076" 0603 96.52,26.035 r180 top value=1uF
C58 "885012206083" 0603 95.583,16.32 r180 top value=1000pF
C59 "885012206095" 0603 110.956,19.948 r0 top value=0.1uF
C60 "885012206076" 0603 67.818,6.477 r90 top value=1uF
C61 "885012206095" 0603 70.929,9.392 r180 top value=0.1uF
C62 "885012207103" 0805_HV 110.881,14.055 r180 top value=1uF
C63 "885012107014" 0805_150 114.325,14.427 r90 top value=10uF
C64 "885012206095" 0603 118.823,16.943 r0 top value=0.1uF
C65 "885012206076" 0603 118.823,11.568 r180 top value=1uF
C66 "885012206076" 0603 95.758,3.302 r180 top value=1uF
C67 "885012206076" 0603 76.073,5.842 r180 top value=1uF
C68 "885012206076" 0603 125.725,46.99 r180 top value=1uF
C69 "885012206095" 0603 125.725,48.63 r180 top value=0.1uF
C70 "885012206083" 0603 130.473,61.153 r0 top value=1000pF
C72 "885012206083" 0603 130.486,65.024 r0 top value=1000pF
C73 "885012206083" 0603 130.473,66.84 r0 top value=1000pF
C74 "GRJ32ER71H106KE11L" 1210_280 111.753,54.802 r180 top value=10uF
C75 "GRJ32ER71H106KE11L" 1210_280 111.76,51.216 r180 top value=10uF
C76 "885012207103" 0805_HV 109.601,34.29 r180 top value=1uF
C77 "885012206095" 0603 109.601,32.258 r0 top value=0.1uF
C100 "885012207103" 0805_HV 80.01,25.908 r0 top value=1uF
C101 "EKZM350ELL471MJ16S" FP-EKZM350ELL681MJ25S_RADIAL-MFG 152.273,23.749 r0 top value=470µF
D1 "BAV21WS-TP" SOD-323 77.05,21.577 r180 top value=250V
D2 "BAV21WS-TP" SOD-323 76.95,19.54 r180 top value=250V
D3 "GBU4J-BP" GBU 31.962,44.01 r270 top value=600V
D4 "824550431" SMC_265 36.576,81.407 r270 top value=43V
D5 "824550431" SMC_265 43.18,81.407 r90 top value=43V
D6 "MURA160T3G" SMA 62.484,78.74 r90 top value=600V
D7 "CMDZ18L" SOD-323 72.79,21.577 r180 top value=18V
D8 "CMDZ12L" SOD-323 72.771,17.272 r180 top value=12V
D9 "ES1JFL" MINI-SMA 54.229,22.86 r180 top value=600V
D10 "ES1JFL" MINI-SMA 54.229,26.162 r180 top value=600V
D11 "BAV70-E3-08" SOT-23L 74.168,32.258 r0 top value=70V
D12 "BAV21WS-TP" SOD-323 60.165,51.34 r90 top value=250V
D13 "BAV21WS-TP" SOD-323 62.335,43.308 r0 top value=250V
D14 "CMDZ15L" SOD-323 62.335,41.271 r0 top value=15V
D15 "CMDZ12L" SOD-323 103.124,34.417 r270 top value=12V
D16 "BAV21WS-TP" SOD-323 42.926,48.26 r0 top value=250V
D17 "MMSZ5254BS-7-F" SOD-323 100.632,28.12 r180 top value=27V
D18 "BAT46WJ,115" SOD-323F 132.08,28.194 r0 top value=100V
D19 "BAT46WJ,115" SOD-323F 132.08,26.289 r0 top value=100V
D20 "150120VS75000" WL_SMCW_GREEN_1206 111.04,8.383 r90 top value=Green
D21 "150120VS75000" WL_SMCW_GREEN_1206 115.866,8.383 r90 top value=Green
D22 "150120VS75000" WL_SMCW_GREEN_1206 120.695,8.383 r90 top value=Green
D23 "MBR0530T1G" SOD-123 76.327,8.89 r0 top value=30V
D24 "MBR0530T1G" SOD-123 76.327,3.429 r0 top value=30V
D25 "CMDZ15L" SOD-323 121.158,48.895 r180 top value=15V
D26 "BAT46WJ,115" SOD-323F 105.41,13.832 r90 top value=100V
D27 "BAT46WJ,115" SOD-323F 105.41,17.666 r90 top value=100V
D28 "BAT46WJ,115" SOD-323F 105.41,21.377 r90 top value=100V
D29 "CMDZ15L" SOD-323 159.664,13.767 r270 top value=15V
D30 "MMSZ4689T3G" SOD-123 157.988,6.629 r180 top value=5.1V
D31 "BAS40-04-7-F" SOT-23L 158.191,9.449 r90 top value=40V
D100 "CMDZ15L" SOD-323 71.247,29.21 r0 top value=15V
D101 "BAT46W" SOD-323F 76.327,29.972 r270 top value=100V
D102 "CMDZ5255B" SOD-323 120.65,59.944 r90 top value=28V
D103 "824550431" SMC_265 49.784,81.407 r270 top value=43V
D104 "824550431" SMC_265 56.388,81.407 r90 top value=43V
F1 "39213150000" FUSE_392 32.52,9.743 r270 top
H1 "V6560W" HSINK_V6560W 26.645,44.01 r270 top value=10C/W
H2 "6230DG" FP-6230DG_PTH_HTSNK-MFG 49.046,67.31 r180 top
J1 "691236510003" Wurth_691236510003 170.65,25.963 r90 top
J2 "691236510003" Wurth_691236510003 170.65,41.91 r90 top
J3 "61302021821" BoosterPack_40pin_J1J3 125.806,62.687 r180 bottom
J4 "61302021821" BoosterPack_40pin_J2J4 168.986,62.687 r180 bottom
J5 "22-05-3041" FP-22-05-3041_HDR4-MFG 104.14,2.54 r0 top
J6 "HTSW-103-07-G-D" Samtec_HTSW-103-07-x-D 101.567,15.347 r180 top
L1 "7447060" FP-7447010_RADIAL-MFG 45.847,19.812 r0 top value=330uH
L2 "744822222" WE-CMB_Type_S 30.48,21.15 r180 top value=2.2mH
L3 "744325550" WE-HC6 140.072,26.801 r270 top value=5.5uH
L4 "74438323100" WE-MAPI_2510 114.351,18.009 r270 top value=10uH
LOGO1 "DANGER HIGH VOLTAGE" IEC_HighVoltage_Small 20.955,14.732 r0 top
LOGO2 "DANGER HIGH VOLTAGE" IEC_HighVoltage_Small 63.627,12.827 r0 top
LOGO3 "DANGER HIGH VOLTAGE" IEC_HighVoltage_Small 58.039,60.706 r0 top
LOGO4 "DANGER HIGH VOLTAGE" IEC_HighVoltage_Small 30.226,85.344 r0 top
Logo5 "CAUTION HOT SURFACE" IEC_HotSurface_Small 21.717,43.688 r0 top
NT1 "Net-Tie" Net-Tie_10milWide_30milLong 119.38,23.774 r0 top net-tie
NT2 "Net-Tie" Net-Tie_50milWide_30milLong 46.355,57.785 r90 top net-tie
Q1 "MMBT3904-7-F" SOT-23 75.565,24.384 r180 top value="40 V"
Q2 "SPD08N50C3" DPAK 64.516,29.718 r180 top
Q3 "MMBT3904-7-F" SOT-23 71.12,24.384 r180 top value="40 V"
Q4 "MMBT3904-7-F" SOT-23 62.06,46.178 r90 top value="40 V"
Q5 "NTB7D3N15MC" DDPAK 113.03,70.278 r90 top
Q6 "IPA65R225C7XKSA1" TO-220FP 49.046,69.85 r0 top
Q7 "MMBT3904-7-F" SOT-23 45.867,42.493 r270 top value="40 V"
Q8 "MMBT3906-7-F" SOT-23 49.784,42.672 r90 top value="40 V"
Q11 "CSD18534Q5A" DQJ0008A 120.65,53.975 r90 top value=60V
Q12 "CSD18534Q5A" DQJ0008A 120.65,44.45 r270 top value=60V
Q13 "CSD18534Q5A" DQJ0008A 142.748,7.975 r180 top value=60V
Q14 "CSD18534Q5A" DQJ0008A 151.101,7.983 r0 top value=60V
Q15 "NTTFS5C670NLTAG" Power_WDFN-8 130.629,35.519 r180 top
Q16 "NTTFS5C670NLTAG" Power_WDFN-8 129.529,17.341 r180 top
Q17 "NTTFS5C670NLTAG" Power_WDFN-8 135.162,35.523 r270 top
Q18 "NTTFS5C670NLTAG" Power_WDFN-8 133.997,17.472 r90 top
Q19 "RS3L110ATTB1" FP-SQ9407EY-T1_GE3_SO-8-MFG 163.982,14.529 r0 top
Q100 "MMBT3904-7-F" SOT-23 80.264,30.353 r90 top value="40 V"
R1 "RC0603FR-07470RL" 0603 92.583,20.574 r90 top value=470
R2 "MCR18EZPJ000" 1206 67.31,35.56 r0 top value=0
R3 "ERJ-8ENF4993V" 1206 72.39,35.56 r180 top value=499k
R4 "MCR18EZPJ000" 1206 62.23,35.56 r0 top value=0
R5 "ERJ-8ENF4993V" 1206 77.47,35.56 r180 top value=499k
R6 "RC0603FR-071KL" 0603 79.375,23.495 r180 top value=1.00k
R7 "CRM2010-JW-4R7ELF" 2010 36.83,9.83 r270 top value=4.7
R8 "CRM2010-JW-4R7ELF" 2010 36.83,32.58 r270 top value=4.7
R9 "RC0603FR-071KL" 0603 74.295,28.829 r90 top value=1.00k
R10 "RC0603FR-071KL" 0603 73.025,19.558 r0 top value=1.00k
R11 "RC0603FR-071KL" 0603 71.12,27.178 r180 top value=1.00k
R12 "CRCW25125R60JNEG" 2512 65.151,84.455 r180 top value=5.6
R13 "560050316012" FP-560050316012_0603-MFG 60.165,54.494 r90 top
R14 "RC0603FR-074K75L" 0603 59.52,46.678 r90 top value=4.75k
R15 "RC1206FR-07750KL" 1206 56.007,30.04 r270 top value=750k
R16 "ESR03EZPJ101" 0603 122.174,58.674 r270 top value=100
R17 "DNP" 1206 120.86,69.778 r270 top
R18 "RT0603DRE07271KL" 0603 55.626,42.926 r0 top value=271k
R19 "RC1206FR-07750KL" 1206 56.515,35.56 r270 top value=750k
R20 "RC0603FR-074K75L" 0603 109.601,28.702 r0 top value=4.75k
R21 "CRCW0603100KDHEAP" 0603 55.574,54.969 r0 top value=100k
R22 "RMCF0603ZT0R00" 0603 44.223,63.271 r90 top value=0
R23 "RC0603FR-071KL" 0603 51.853,55.444 r90 top value=1.00k
R24 "ERJ-6ENF2211V" 0805_HV 106.045,34.671 r270 top value=2.21k
R25 "RC0603FR-079K53L" 0603 55.626,53.34 r180 top value=9.53k
R26 "ERJ-3EKF3002V" 0603 55.626,46.736 r180 top value=30.0k
R27 "560050363011" 2512 49.279,64.821 r0 top value=0.5
R28 "560050363011" 2512 49.224,60.325 r0 top value=0.5
R29 "RC0603FR-071K5L" 0603 95.758,36.195 r0 top value=1.50k
R30 "RC0603FR-0710KL" 0603 42.926,46.482 r0 top value=10.0k
R31 "RC0603FR-072K21L" 0603 92.71,35.306 r90 top value=2.21k
R32 "RT0603DRE0786K6L" 0603 100.954,29.858 r0 top value=86.6k
R33 "RC0603FR-071KL" 0603 100.844,26.31 r180 top value=1.00k
R34 "RC0603FR-0747KL" 0603 98.552,33.274 r90 top value=47.0k
R35 "RC0603FR-0720KL" 0603 50.279,46.68 r0 top value=20.0k
R36 "RC0603FR-074K75L" 0603 52.578,42.672 r270 top value=4.75k
R37 "RC0603FR-0710KL" 0603 93.265,29.124 r90 top value=10.0k
R46 "580070763001" 2512 120.65,38.735 r0 top value=0.002
R47 "560050316012" FP-560050316012_0603-MFG 122.555,33.655 r90 top
R48 "560050316012" FP-560050316012_0603-MFG 127.216,33.723 r90 top
R49 "RMCF0603ZT0R00" 0603 131.953,31.75 r0 top value=0
R50 "RMCF0603ZT0R00" 0603 131.953,22.606 r180 top value=0
R51 "RMCF0603ZT0R00" 0603 131.953,29.972 r180 top value=0
R52 "RMCF0603ZT0R00" 0603 131.953,24.384 r180 top value=0
R53 "560050316012" FP-560050316012_0603-MFG 124.838,19.322 r180 top
R54 "RMCF0603ZT0R00" 0603 123.538,29.539 r270 top value=0
R55 "580070763005" 2512 151.101,13.171 r180 top value=0.005
R56 "RC0603FR-07113KL" 0603 119.634,34.798 r270 top value=113k
R57 "560050316012" FP-560050316012_0603-MFG 121.59,19.177 r0 top
R58 "RT0603DRE072K58L" 0603 117.729,34.798 r90 top value=2.58k
R59 "RC0603FR-07249KL" 0603 118.603,19.105 r180 top value=249k
R60 "RC0603FR-0715KL" 0603 114.935,21.031 r180 top value=15.0k
R61 "RT0603DRE074K22L" 0603 115.824,34.798 r270 top value=4.22k
R62 "RC0603FR-071KL" 0603 113.274,7.975 r90 top value=1.00k
R63 "RC0603FR-071KL" 0603 118.098,7.975 r90 top value=1.00k
R64 "RC0603FR-071KL" 0603 122.907,7.975 r90 top value=1.00k
R65 "RC0603FR-0766K5L" 0603 109.601,30.48 r0 top value=66.5k
R66 "CRCW060324K3FKEA" 0603 109.601,23.495 r0 top value=24.3k
R67 "RC0603FR-074K99L" 0603 109.601,21.844 r0 top value=4.99k
R68 "RT0603BRD0730K1L" 0603 109.601,26.924 r0 top value=30.1k
R69 "RT0603BRD075K23L" 0603 109.601,25.146 r180 top value=5.23k
R70 "RC1206FR-07750KL" 1206 54.737,19.558 r0 top value=750k
R71 "RC0603FR-0710KL" 0603 95.382,9.066 r0 top value=10.0k
R72 "RC1206FR-07750KL" 1206 54.737,16.002 r180 top value=750k
R73 "RC0603FR-0710KL" 0603 95.591,12.991 r0 top value=10.0k
R74 "RC0603FR-0710KL" 0603 95.591,14.676 r0 top value=10.0k
R75 "RC0603FR-0722KL" 0603 71.12,14.097 r270 top value=22.0k
R76 "RC0603FR-0710KL" 0603 95.64,23.615 r0 top value=10.0k
R77 "RC0603FR-0788K7L" 0603 107.546,13.528 r270 top value=88.7k
R78 "RC0603FR-0722KL" 0603 107.546,16.936 r270 top value=22.0k
R79 "RC0603FR-0710KL" 0603 105.41,25.1 r90 top value=10.0k
R80 "RC0603FR-074K75L" 0603 124.53,77.898 r90 top value=4.75k
R81 "RC0603FR-074K75L" 0603 126.289,77.898 r90 top value=4.75k
R82 "RC0603FR-074K75L" 0603 128.104,77.969 r90 top value=4.75k
R84 "CRCW0603110KFKEA" 0603 134.222,65.024 r0 top value=110k
R85 "CRCW0603110KFKEA" 0603 138.032,65.024 r0 top value=110k
R86 "RC0603FR-0710KL" 0603 134.222,63.411 r0 top value=10.0k
R87 "RC0603FR-0710KL" 0603 138.012,63.411 r0 top value=10.0k
R88 "CRCW0603100KDHEAP" 0603 160.655,22.352 r0 top value=100k
R89 "CRCW0603100KDHEAP" 0603 160.655,25.654 r0 top value=100k
R90 "RMCF0603ZT0R00" 0603 120.999,65.024 r270 top value=0
R93 "CRCW20101K00FKEF" 2010 166.649,8.026 r0 top value=1.00k
R94 "CRCW0603100KDHEAP" 0603 163.982,11.1 r180 top value=100k
R100 "CRCW0603100KDHEAP" 0603 77.978,30.226 r90 top value=100k
R101 "CRCW0603100KDHEAP" 0603 80.264,27.813 r0 top value=100k
R102 "CRCW0603475KFKEA" 0603 121.158,34.798 r270 top value=475k
T1 "750320256r00H" FP-750320256r00H_TRANSFORMER_41MM9_44MM0-MFG 86.36,59.56 r0 top
T2 "750313638" Wurth_750313638 85.598,6.477 r180 top value=340uH
TP1 "5012" Keystone5012 58.573,8.785 r90 top
TP2 "5012" Keystone5012 28.194,8.89 r90 top
U1 "SFH6156-2" SMD-4 85.598,20.066 r180 top
U2 "UCC24612-1DBVR" DBV0005A_N 115.515,59.917 r0 top
U3 "UCC28050DR" D0008A_N 49.224,50.684 r180 top
U4 "SFH6156-2" SMD-4 85.598,34.544 r180 top
U5 "TL431AIDBZT" DBZ0003A_N 96.52,29.21 r270 top
U7 "BQ25751RRVT" RRV0036A-MFG 117.297,27.28 r0 top
U8 "AMC1311BDWVR" DWV0008A 85.598,14.351 r0 top
U9 "TLV6001IDBVR" DBV0005A_N 100.844,21.815 r0 top value=TLV6001UIDBVR
U10 "TLV70450DBVR" DBV0005A_N 70.929,6.247 r270 top
U11 "TPS560430YDBVR" DBV0006A_N 110.956,17.003 r0 top
U12 "SN6501DBVR" DBV0005A_N 95.365,6.247 r0 top
U13 "TLV70433DBVR" DBV0005A_N 118.823,14.275 r0 top

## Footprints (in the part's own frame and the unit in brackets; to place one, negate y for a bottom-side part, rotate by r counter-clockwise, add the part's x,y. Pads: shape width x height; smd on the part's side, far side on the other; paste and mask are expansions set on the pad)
0603 [mm] "0603 from SM-752 data"
  rect 1x0.95 smd: 1(-0.8,0) 2(0.8,0)
  silkscreen extent -1.52,-0.69 1.52,0.69, body extent -0.87,-0.47 0.87,0.47, height 1
0805_150 [mm] "0805 / 1.5 mm height"
  rect 1.15x1.45 smd: 1(-0.9,0) 2(0.9,0)
  silkscreen extent -0.1,-0.8 0.1,0.8, body extent -1.1,-0.72 1.1,0.72, height 1.5
0805_HV [mil] "0805 with 30mil clearance between pads"
  rect 50x63 smd: 1(-40,0) 2(40,0)
  silkscreen extent -74,-40 74,40, body extent -43,-29 43,29, height 57
1206 [mm] "1206 from SM-752 data"
  rect 1.3x1.85 smd: 1(-1.45,0) 2(1.45,0)
  silkscreen extent -2.4,-1.21 2.4,1.21, body extent -1.7,-0.9 1.7,0.9, height 1.35
1206_180 [mm] "1206_180"
  rect 1.1x1.6 smd: 1(-1.7,0) 2(1.7,0)
  silkscreen extent -0.9,-1 0.9,1, body extent -1.75,-0.95 1.75,0.95, height 1.8
1210_280 [mm] "SMD, 2-Leads, Body 3.6x2.8mm, Height 2.8mm"
  rect 1.1x2.2 smd: 1(-1.65,0) 2(1.65,0)
  silkscreen extent -0.84,-1.4 0.84,1.4, body extent -1.8,-1.4 1.8,1.4, height 2.8
2010 [mm] "Chip Capacitor, Body 5.08x2.54mm, IPC Medium Density"
  rect 1.6x2.7 smd: 1(-2.3,0) 2(2.3,0)
  silkscreen extent -3.42,-1.65 3.42,1.65, body extent -2.73,-1.45 2.73,1.45, height 1.66
2512 [mm] "Chip Resistor, Body 6.3x3.2mm, IPC Medium Density"
  rect 1.3x3.4 smd: 1(-2.95,0) 2(2.95,0)
  silkscreen extent -1.9,-1.6 1.9,1.6, body extent -3.22,-1.67 3.22,1.67, height 0.71
B32923_16.5mm_10.5 [mm] "Epcos film capacitors, 22.5mm spacing"
  rect 1.5x1.5 hole 1: 1(-11.25,0)
  round 1.5 hole 1: 2(11.25,0)
  silkscreen extent -13.25,-5.25 13.25,5.25, body extent -13.25,-5.25 13.25,5.25, height 16.5
BoosterPack_40pin_J1J3 [mm] "Receptacle, 2.54mm, 10x2, TH"
  rrect6% 1.55x1.55 hole 1.02: 1(1.27,-11.43)
  round 1.55 hole 1.02: 2(1.27,-8.89) 3(1.27,-6.35) 4(1.27,-3.81) 5(1.27,-1.27) 6(1.27,1.27) 7(1.27,3.81) 8(1.27,6.35) 9(1.27,8.89) 10(1.27,11.43) 21(-1.27,-11.43) 22(-1.27,-8.89) 23(-1.27,-6.35) 24(-1.27,-3.81) 25(-1.27,-1.27) 26(-1.27,1.27) 27(-1.27,3.81) 28(-1.27,6.35) 29(-1.27,8.89) 30(-1.27,11.43)
  silkscreen extent -2.48,-12.95 2.48,12.95, body extent -2.48,-12.95 2.48,12.95, height 10.01
BoosterPack_40pin_J2J4 [mm] "Receptacle, 2.54mm, 10x2, TH"
  round 1.55 hole 1.02: 11(-1.27,11.43) 12(-1.27,8.89) 13(-1.27,6.35) 14(-1.27,3.81) 15(-1.27,1.27) 16(-1.27,-1.27) 17(-1.27,-3.81) 18(-1.27,-6.35) 19(-1.27,-8.89) 20(-1.27,-11.43) 31(1.27,11.43) 32(1.27,8.89) 33(1.27,6.35) 34(1.27,3.81) 35(1.27,1.27) 36(1.27,-1.27) 37(1.27,-3.81) 38(1.27,-6.35) 39(1.27,-8.89) 40(1.27,-11.43)
  silkscreen extent -2.48,-12.95 2.48,12.95, body extent -2.48,-12.95 2.48,12.95, height 10.01
CAPPR7.5-18x31.5 [mm] "Capacitor, Electrolytic, Radial; Body 18 x 31.5 mm (Dia.xH typ); Pin Spacing 7.5 mm (typ)"
  rect 1.85x1.85 hole 1.1: 1(-3.75,0)
  round 1.85 hole 1.1: 2(3.75,0)
  silkscreen extent -9,-9 9,9, body extent -9,-9.01 9,9.01, height 33.5
CAPSMT_62_E55 [mm] "5 x 5.2mm:  Chemi-Con E55"
  rect 3x1.6 smd: 1(-2.2,0) 2(2.2,0)
  silkscreen extent -2.75,-2.75 2.75,2.75, body extent -2.75,-2.75 2.75,2.75, height 5.5
CAPSMT_62_F80 [mm] "6.3 x 7.7mm:  Chemi-Con F80"
  rect 3.5x1.6 smd: 1(-2.7,0) 2(2.7,0)
  silkscreen extent -3.36,-3.4 3.44,3.4, body extent -3.4,-3.4 3.44,3.4, height 8
D0008A_N [mm] "SOIC, 8-Leads, Body 4.9x3.9mm, Pitch 1.27mm, IPC Medium Density"
  oval 1.45x0.6 smd: 1(-2.725,1.905) 2(-2.725,0.635) 3(-2.725,-0.635) 4(-2.725,-1.905) 5(2.725,-1.905) 6(2.725,-0.635) 7(2.725,0.635) 8(2.725,1.905)
  silkscreen extent -3.3,-2.5 0.9,2.5, body extent -3,-2.45 3,2.45, height 1.63
DBV0005A_N [mm] "SOT23, 5-Leads, Body 2.9x1.6mm, Pitch 0.95mm, Lead Span 2.8mm, IPC Medium Density"
  rrect17% 1x0.6 smd: 1(-1.375,0.95) 2(-1.375,0) 3(-1.375,-0.95) 4(1.375,-0.95) 5(1.375,0.95)
  silkscreen extent -0.25,-1.55 0.25,1.55, body extent -1.42,-1.46 1.42,1.46, height 1.09
DBV0006A_N [mm] "SOT23, 6-Leads, Body 2.9x1.6mm, Pitch 0.95mm, Lead Span 2.8mm, IPC Medium Density"
  rrect17% 1x0.6 smd: 1(-1.375,0.95) 2(-1.375,0) 3(-1.375,-0.95) 4(1.375,-0.95) 5(1.375,0) 6(1.375,0.95)
  silkscreen extent -1.68,-1.55 0.5,1.55, body extent -1.42,-1.46 1.42,1.46, height 1.12
DBZ0003A_N [mm] "SOT23, 3-Leads, Body 2.9x1.3mm, Pitch 0.95mm, Lead Span 2.4mm, IPC Medium Density"
  rrect17% 1x0.6 smd: 1(-1.2,0.95) 2(-1.2,-0.95) 3(1.2,0)
  silkscreen extent 0.2,-1.5 0.7,1.5, body extent -1.26,-1.46 1.26,1.46, height 0.98
DDPAK [mil] "D2-PAK, 3-Pads, Body 9.7x10.4mm (max), TO-263AB, using Vishay Silionix recommended pad sizes"
  rrect8% 135x49.49 smd: 1(-246.06,100) 3(-246.06,-100)
  rrect1% 355x420 smd paste-181.1: 4(155.51,0)
  silkscreen extent -295,-220 344,220, body extent -295,-202 324,202, height 180
DE1_600x400x900 [mm] "TH, 2-Leads, Dia 6mm, Lead Spacing 10mm"
  round 1.35 hole 0.9: 1(-5,0) 2(5,0)
  silkscreen extent -3,-1.65 3,1.65, body extent -5.35,-2 5.35,2, height 9
DPAK [mm] "D-PAK, 3-Pads, Body 6.22x6.73mm (max), TO-252AA using nominal STEP model"
  rrect6% 2.6x1.6 smd: 1(-3.4,2.28) 3(-3.4,-2.28)
  rrect2% 6.2x5.8 smd paste-3: 2(3.4,0)
  body extent -3.86,-3.29 5.84,3.29, height 2.48
DQJ0008A [mm] "SMD, 8-Leads, Body 5.75x4.9mm"
  rrect39% 0.91x0.51 smd paste-0.05 mask-0.05: 1(-2.795,1.905) 2(-2.795,0.635) 3(-2.795,-0.635) 4(-2.795,-1.905) 5(2.795,-1.905) 6(2.795,-0.635) 7(2.795,0.635) 8(2.795,1.905)
  rrect8% 1.58x1.25 on Top Paste: 9(-0.38,1.45) 9(-0.38,0) 9(-0.38,-1.45) 9(1.4,-1.45) 9(1.4,0) 9(1.4,1.45)
  rrect3% 3.48x4.47 on Top Solder: 9(0.55,0)
  rrect2% 4.49x4.57 smd paste-2.5 mask-2.5: 9(1.005,0)
  silkscreen extent -3,-2.6 3,2.6, body extent -3.13,-2.45 3.13,2.45, height 1.15
DWV0008A [mm] "SOIC, 8-Leads, Body 5.95x7.6mm (max), Pitch 1.27mm"
  rrect17% 1.8x0.6 smd: 1(-5.45,1.905) 2(-5.45,0.635) 3(-5.45,-0.635) 4(-5.45,-1.905) 5(5.45,-1.905) 6(5.45,-0.635) 7(5.45,0.635) 8(5.45,1.905)
  silkscreen extent -6.25,-2.95 2.98,2.95, body extent -5.77,-2.92 5.77,2.93, height 2.67
FP-22-05-3041_HDR4-MFG [mm]
  rrect6% 1.57x1.57 hole 1.02 paste-2539.97 mask+0: 1(-3.81,7.073)
  round 1.57 hole 1.02 paste-2539.97 mask+0: 2(-1.27,7.073) 3(1.27,7.073) 4(3.81,7.073)
  silkscreen extent -6.13,1.03 5.08,6.44, body extent -5.18,-6.28 5.18,7.96, height 0.25
FP-6230DG_PTH_HTSNK-MFG [mm]
  rrect2% 4.55x4.55 hole 3 paste-2539.97 mask+0: 1(-12.385,0.63)
  round 4.55 hole 3 paste-2539.97 mask+0: 2(12.385,0.63)
  silkscreen extent -12.7,-6.35 12.7,6.35, body extent -14.76,-6.45 14.76,6.45, height 0.25
FP-7447010_RADIAL-MFG [mm]
  rrect8% 1.25x1.25 hole 0.75 paste-2539.97 mask+0: 1(-4.5,0)
  round 1.25 hole 0.75 paste-2539.97 mask+0: 2(4.5,0)
  silkscreen extent -4.75,-9.25 4.75,9.25, body extent -5.23,-9.35 5.23,9.35, height 0.25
